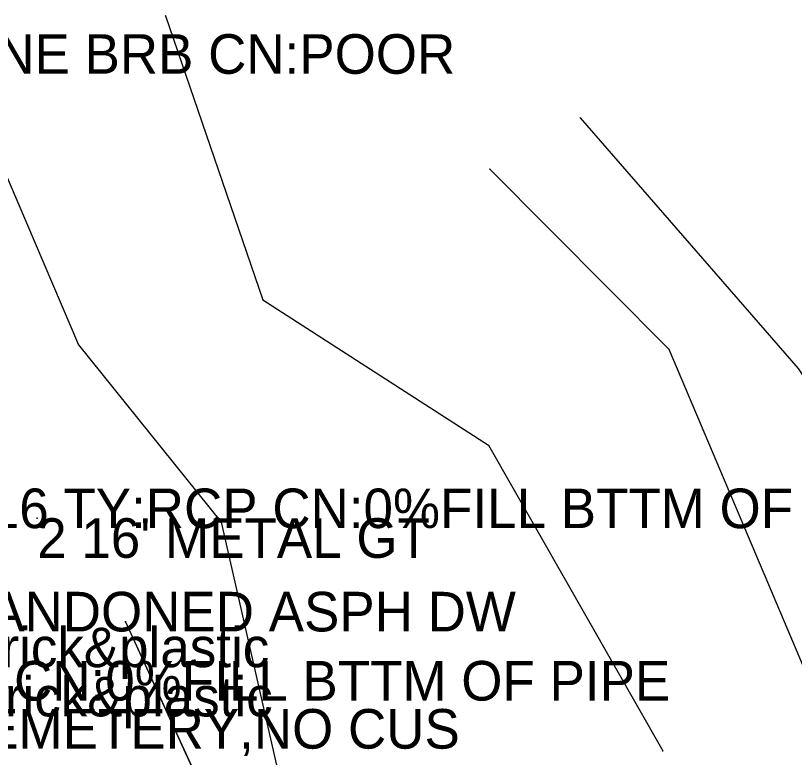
# Model space of a CAD drawing. Extents: x -99999 to 591807, y -99999 to 347168.
# Drawn here: x 589188.3 to 589286.6, y 343966.1 to 344059.8 of the extents above; entities that cross this region are included whole.
import ezdxf

# ---------------------------------------------------------------- set-up
doc = ezdxf.new("R2010")
doc.units = 0
for name, color, linetype in [('S_BREAKLINE', 7, 'Continuous'), ('S_FENCE', 7, 'Continuous'), ('S_FENCE_ANNOT', 7, 'Continuous'), ('S_GATE_ANNOT', 7, 'Continuous'), ('S_GRD_PT_SYM', 7, 'Continuous'), ('S_MSC_PT_SYM', 7, 'Continuous'), ('S_SIDE_DRAIN_ANNOT', 7, 'Continuous'), ('S_SIGN_ANNOT', 7, 'Continuous'), ('S_SURVEY_TEXT_ANNOT', 7, 'Continuous')]:
    doc.layers.add(name, color=color, linetype=linetype)

msp = doc.modelspace()

# ---------------------------------------------------------------- linework, layer by layer
at = {"layer": 'S_BREAKLINE'}
for points in [[(589178.707, 344059.245), (589196.219, 344018.171), (589214.23, 343995.774), (589224.572, 343950.501)], [(589207.211, 344059.713), (589219.516, 344023.844), (589247.989, 344005.526), (589270.012, 343966.925)], [(589259.571, 344046.856), (589287.109, 344015.191), (589313.284, 343975.461), (589338.647, 343911.317), (589374.694, 343882.795), (589378.864, 343824.383), (589432.975, 343780.35), (589441.019, 343746.151)], [(589248.165, 344040.346), (589270.791, 344017.641), (589289.752, 343972.809), (589333.961, 343912.309), (589354.607, 343881.984), (589359.544, 343826.858), (589394.769, 343779.704), (589410.929, 343740.86)], [(589202.172, 343983.211), (589216.682, 343951.497)]]:
    msp.add_lwpolyline(points, dxfattribs=at)
at = {"layer": 'S_FENCE'}
msp.add_line((589202.172, 343983.211), (589216.682, 343951.497), dxfattribs=at)
msp.add_lwpolyline([(589202.172, 343983.211), (589216.682, 343951.497)], dxfattribs=at)
at = {"layer": 'S_GRD_PT_SYM'}
for points in [[(589207.211, 344059.713), (589207.259, 344059.729), (589207.211, 344059.713), (589207.195, 344059.76), (589207.211, 344059.713), (589207.164, 344059.697), (589207.211, 344059.713), (589207.228, 344059.666)], [(589259.571, 344046.856), (589259.609, 344046.889), (589259.571, 344046.856), (589259.538, 344046.894), (589259.571, 344046.856), (589259.533, 344046.823), (589259.571, 344046.856), (589259.604, 344046.818)], [(589248.165, 344040.346), (589248.201, 344040.381), (589248.165, 344040.346), (589248.13, 344040.381), (589248.165, 344040.346), (589248.13, 344040.31), (589248.165, 344040.346), (589248.2, 344040.31)], [(589219.516, 344023.844), (589219.543, 344023.887), (589219.516, 344023.844), (589219.474, 344023.872), (589219.516, 344023.844), (589219.489, 344023.802), (589219.516, 344023.844), (589219.558, 344023.817)], [(589196.219, 344018.171), (589196.258, 344018.202), (589196.219, 344018.171), (589196.187, 344018.21), (589196.219, 344018.171), (589196.18, 344018.14), (589196.219, 344018.171), (589196.25, 344018.132)], [(589270.791, 344017.641), (589270.837, 344017.661), (589270.791, 344017.641), (589270.771, 344017.687), (589270.791, 344017.641), (589270.745, 344017.622), (589270.791, 344017.641), (589270.81, 344017.595)], [(589247.989, 344005.526), (589248.033, 344005.551), (589247.989, 344005.526), (589247.964, 344005.57), (589247.989, 344005.526), (589247.946, 344005.501), (589247.989, 344005.526), (589248.014, 344005.483)], [(589214.23, 343995.774), (589214.279, 343995.785), (589214.23, 343995.774), (589214.219, 343995.822), (589214.23, 343995.774), (589214.181, 343995.762), (589214.23, 343995.774), (589214.241, 343995.725)], [(589202.172, 343983.211), (589202.217, 343983.232), (589202.172, 343983.211), (589202.151, 343983.256), (589202.172, 343983.211), (589202.127, 343983.19), (589202.172, 343983.211), (589202.193, 343983.165)], [(589270.012, 343966.925), (589270.055, 343966.949), (589270.012, 343966.925), (589269.987, 343966.968), (589270.012, 343966.925), (589269.968, 343966.9), (589270.012, 343966.925), (589270.037, 343966.881)]]:
    msp.add_lwpolyline(points, close=True, dxfattribs=at)
at = {"layer": 'S_MSC_PT_SYM'}
for points in [[(589191.023, 343996.277), (589191.023, 343996.327), (589191.023, 343996.277), (589190.973, 343996.277), (589191.023, 343996.277), (589191.023, 343996.227), (589191.023, 343996.277), (589191.073, 343996.277)], [(589202.172, 343983.211), (589202.172, 343983.261), (589202.172, 343983.211), (589202.122, 343983.211), (589202.172, 343983.211), (589202.172, 343983.161), (589202.172, 343983.211), (589202.222, 343983.211)]]:
    msp.add_lwpolyline(points, dxfattribs=at)

# ---------------------------------------------------------------- texts
at = {"layer": 'S_FENCE_ANNOT'}
msp.add_text("3'WEB ONE BRB CN:POOR", height=5, dxfattribs=at).set_placement((589158.57, 344052.409))
at = {"layer": 'S_GATE_ANNOT'}
msp.add_text("2 16' METAL GT", height=5, dxfattribs=at).set_placement((589191.023, 343991.277))
at = {"layer": 'S_SIDE_DRAIN_ANNOT'}
for s, p in [('DI:16 TY:RCP CN:0%FILL BTTM OF ', (589176.494, 343995.028)), ('CN:0%FILL BTTM OF PIPE', (589188.098, 343973.255))]:
    msp.add_text(s, height=5, dxfattribs=at).set_placement(p)
at = {"layer": 'S_SIGN_ANNOT'}
for p in [(589112.18, 343977.468), (589112.616, 343971.254)]:
    msp.add_text('white bluff cemetery,na,brick&plastic', height=5, dxfattribs=at).set_placement(p)
at = {"layer": 'S_SURVEY_TEXT_ANNOT'}
for s, p in [('ABANDONED ASPH DW', (589176.044, 343981.985)), ('ASPH DW TO CEMETERY,NO CUS', (589135.167, 343967.181))]:
    msp.add_text(s, height=5, dxfattribs=at).set_placement(p)

doc.saveas('drawing.dxf')
